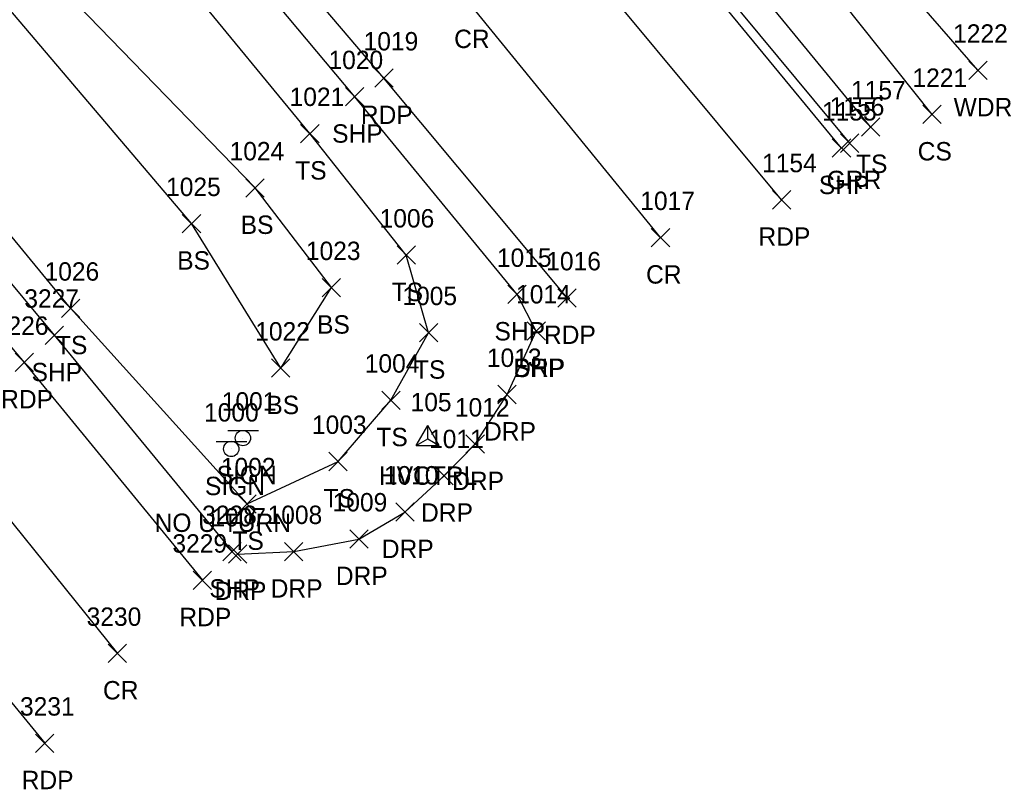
# Model space of a CAD drawing. Extents: x 1647574 to 1652703, y 212895 to 228670.
# Drawn here: x 1650120.6 to 1650228.4, y 225965.1 to 226048.7 of the extents above; entities that cross this region are included whole.
import ezdxf

# ---------------------------------------------------------------- set-up
doc = ezdxf.new("R2010")
doc.units = 0
for name, color, linetype in [('C_A', 7, 'Continuous'), ('C_I', 7, 'Continuous'), ('CPSM', 7, 'Continuous'), ('L_A', 7, 'Continuous'), ('L_I', 7, 'Continuous'), ('L_TIC', 7, 'Continuous'), ('LAWA', 7, 'Continuous'), ('LELB', 7, 'Continuous'), ('P_A', 7, 'Continuous'), ('P_I', 7, 'Continuous'), ('P_TIC', 7, 'Continuous'), ('PET', 7, 'Continuous'), ('PRC', 7, 'Continuous'), ('PSP', 7, 'Continuous'), ('R_A', 7, 'Continuous'), ('R_I', 7, 'Continuous'), ('R_TIC', 7, 'Continuous'), ('RDP', 7, 'Continuous'), ('RGR', 7, 'Continuous'), ('S_A', 7, 'Continuous'), ('S_C', 7, 'Continuous'), ('S_I', 7, 'Continuous'), ('SSGN', 7, 'Continuous')]:
    doc.layers.add(name, color=color, linetype=linetype)

msp = doc.modelspace()

# ---------------------------------------------------------------- linework, layer by layer
at = {"layer": 'CPSM'}
for p, q in [((1650163.72, 226002.47), (1650164.97, 226004.64)), ((1650166.22, 226002.47), (1650164.97, 226004.64)), ((1650164.97, 226003.19), (1650164.97, 226004.64)), ((1650163.72, 226002.47), (1650164.97, 226003.19)), ((1650163.72, 226002.47), (1650166.22, 226002.47)), ((1650164.97, 226003.19), (1650164.97, 226003.19)), ((1650164.97, 226003.19), (1650166.22, 226002.47))]:
    msp.add_line(p, q, dxfattribs=at)
at = {"layer": 'L_TIC'}
for points in [[(1650223.82, 226042.26), (1650225.82, 226044.26)], [(1650225.82, 226042.26), (1650223.82, 226044.26)], [(1650218.83, 226037.46), (1650220.83, 226039.46)], [(1650220.83, 226037.46), (1650218.83, 226039.46)], [(1650212.15, 226036.1), (1650214.15, 226038.1)], [(1650214.15, 226036.1), (1650212.15, 226038.1)], [(1650151.14, 226035.38), (1650153.14, 226037.38)], [(1650153.14, 226035.38), (1650151.14, 226037.38)], [(1650145.18, 226029.47), (1650147.18, 226031.47)], [(1650147.18, 226029.47), (1650145.18, 226031.47)], [(1650138.27, 226025.59), (1650140.27, 226027.59)], [(1650140.27, 226025.59), (1650138.27, 226027.59)], [(1650161.63, 226022.17), (1650163.63, 226024.17)], [(1650163.63, 226022.17), (1650161.63, 226024.17)], [(1650153.49, 226018.63), (1650155.49, 226020.63)], [(1650155.49, 226018.63), (1650153.49, 226020.63)], [(1650125.11, 226016.39), (1650127.11, 226018.39)], [(1650127.11, 226016.39), (1650125.11, 226018.39)], [(1650164.06, 226013.73), (1650166.06, 226015.73)], [(1650166.06, 226013.73), (1650164.06, 226015.73)], [(1650147.97, 226009.88), (1650149.97, 226011.88)], [(1650149.97, 226009.88), (1650147.97, 226011.88)], [(1650147.97, 226009.88), (1650149.97, 226011.88)], [(1650149.97, 226009.88), (1650147.97, 226011.88)], [(1650159.97, 226006.39), (1650161.97, 226008.39)], [(1650161.97, 226006.39), (1650159.97, 226008.39)], [(1650154.22, 225999.73), (1650156.22, 226001.73)], [(1650156.22, 225999.73), (1650154.22, 226001.73)], [(1650144.31, 225995.12), (1650146.31, 225997.12)], [(1650146.31, 225995.12), (1650144.31, 225997.12)], [(1650144.31, 225995.12), (1650146.31, 225997.12)], [(1650146.31, 225995.12), (1650144.31, 225997.12)]]:
    msp.add_lwpolyline(points, dxfattribs=at)
at = {"layer": 'LAWA'}
msp.add_lwpolyline([(1650224.82, 226043.26), (1650200.57, 226071.14), (1650179.14, 226096.39), (1650156.93, 226122.13), (1650126.46, 226158.5), (1650102.32, 226186.03), (1650070.86, 226221.7), (1650047.25, 226248.26), (1650033.72, 226259.55), (1650015.55, 226280.28), (1649981.36, 226313.37), (1649950.59, 226346.36), (1649922.81, 226373.8), (1649891.44, 226407.34), (1649856.77, 226439.08), (1649829.63, 226467.03), (1649787.56, 226504.18), (1649754.94, 226535.2), (1649724.22, 226565.72), (1649692.31, 226598.17), (1649653.67, 226635.29), (1649620.52, 226666.86), (1649581.67, 226703.66)], dxfattribs=at)
at = {"layer": 'LELB'}
for points in [[(1650213.15, 226037.1), (1650185.87, 226070.33), (1650156.97, 226103.72), (1650126.82, 226139.03), (1650097.45, 226172.49), (1650065.12, 226208.19), (1650039.15, 226236.7), (1650005.62, 226272.51), (1649977.06, 226302.34), (1649946.85, 226333.69), (1649915.81, 226365.02), (1649884.88, 226395.87), (1649852.74, 226426.8), (1649817.4, 226461.44), (1649778.8, 226498.35), (1649747.79, 226526.99), (1649716.78, 226556.99), (1649685.05, 226589.65), (1649647.22, 226623.29), (1649611.68, 226660.43), (1649573.8, 226694.76)], [(1650145.31, 225996.12), (1650155.22, 226000.73), (1650160.97, 226007.39), (1650165.06, 226014.73), (1650162.63, 226023.17), (1650152.14, 226036.38), (1650125.52, 226068.74), (1650101.36, 226098.15), (1650073.79, 226131.47), (1650039.14, 226169.85), (1650006.52, 226208.67), (1649978.85, 226238.77), (1649944.11, 226276), (1649910.77, 226309.61), (1649879.19, 226341.22), (1649849.26, 226371.24), (1649815.2, 226404.44), (1649786.47, 226431.97), (1649749.39, 226466.79), (1649718.31, 226495.58), (1649694.54, 226518.32), (1649659.53, 226550.77), (1649625.91, 226582.74), (1649593.12, 226613.01)], [(1650145.31, 225996.12), (1650126.11, 226017.39), (1650101.66, 226047.08), (1650074.02, 226078.27), (1650048.35, 226107.52), (1650011.02, 226148.89), (1649978.29, 226184.76), (1649948.32, 226216.56), (1649918.31, 226248.62), (1649881.09, 226286.67), (1649854.51, 226315.1), (1649822.53, 226345.57), (1649790.94, 226377.4), (1649759.46, 226406.66), (1649722.98, 226440.72), (1649699.36, 226464.18), (1649670.41, 226492.35), (1649633.05, 226526.99), (1649601.72, 226556.3), (1649565.56, 226590.44)], [(1650148.97, 226010.88), (1650139.27, 226026.59), (1650113.43, 226057), (1650088.3, 226087.98), (1650061.28, 226120.08), (1650026.24, 226159.75), (1649992.44, 226196.13), (1649963.33, 226228.07), (1649931.94, 226262.56), (1649896.29, 226297.95), (1649867.38, 226328.16), (1649836.11, 226358.29), (1649802.88, 226390.85), (1649773.49, 226418.93), (1649757.57, 226433.02), (1649733.38, 226449.67), (1649721.38, 226464.7), (1649717.89, 226468.09), (1649721.1, 226472.27), (1649725.43, 226467.47)], [(1650148.97, 226010.88), (1650154.49, 226019.63), (1650146.18, 226030.47), (1650117.14, 226060.39), (1650092.92, 226091.65), (1650065.04, 226122.85), (1650030.31, 226163.04), (1649996.06, 226198.8), (1649967.82, 226231.08), (1649935.01, 226265.64), (1649900.92, 226301.66), (1649869, 226330.3), (1649837.58, 226359.92), (1649804, 226392.67), (1649775.11, 226420.09), (1649758.52, 226434.35), (1649738.4, 226455.19), (1649725.43, 226467.47)], [(1650219.83, 226038.46), (1650194.8, 226069.92), (1650172.81, 226091.36), (1650150.41, 226121.08), (1650123.6, 226156.67)]]:
    msp.add_lwpolyline(points, dxfattribs=at)
at = {"layer": 'P_TIC'}
for points in [[(1650159.2, 226041.42), (1650161.2, 226043.42)], [(1650161.2, 226041.42), (1650159.2, 226043.42)], [(1650156.03, 226039.39), (1650158.03, 226041.39)], [(1650158.03, 226039.39), (1650156.03, 226041.39)], [(1650208.98, 226033.8), (1650210.98, 226035.8)], [(1650210.98, 226033.8), (1650208.98, 226035.8)], [(1650202.46, 226028.18), (1650204.46, 226030.18)], [(1650204.46, 226028.18), (1650202.46, 226030.18)], [(1650189.29, 226024.07), (1650191.29, 226026.07)], [(1650191.29, 226024.07), (1650189.29, 226026.07)], [(1650173.69, 226017.89), (1650175.69, 226019.89)], [(1650175.69, 226017.89), (1650173.69, 226019.89)], [(1650179.12, 226017.51), (1650181.12, 226019.51)], [(1650181.12, 226017.51), (1650179.12, 226019.51)], [(1650123.34, 226013.45), (1650125.34, 226015.45)], [(1650125.34, 226013.45), (1650123.34, 226015.45)], [(1650175.78, 226013.91), (1650177.78, 226015.91)], [(1650177.78, 226013.91), (1650175.78, 226015.91)], [(1650120.07, 226010.5), (1650122.07, 226012.5)], [(1650122.07, 226010.5), (1650120.07, 226012.5)], [(1650142.68, 225989.93), (1650144.68, 225991.93)], [(1650144.68, 225989.93), (1650142.68, 225991.93)], [(1650139.46, 225986.82), (1650141.46, 225988.82)], [(1650141.46, 225986.82), (1650139.46, 225988.82)], [(1650130.21, 225978.86), (1650132.21, 225980.86)], [(1650132.21, 225978.86), (1650130.21, 225980.86)], [(1650122.3, 225969.1), (1650124.3, 225971.1)], [(1650124.3, 225969.1), (1650122.3, 225971.1)]]:
    msp.add_lwpolyline(points, dxfattribs=at)
at = {"layer": 'PET'}
for points in [[(1650203.46, 226029.18), (1650176.21, 226061.89), (1650147.53, 226095.79), (1650117.29, 226130.73), (1650087.4, 226164.52), (1650055.9, 226199.34), (1650029.44, 226228.14), (1649996.95, 226263.47), (1649968.15, 226293.72), (1649938.19, 226324.52), (1649906.65, 226356.13), (1649876.52, 226386.27), (1649843.75, 226418.81), (1649809.66, 226451.94), (1649770.32, 226489.71), (1649739.98, 226518.42), (1649716.1, 226541.38), (1649682.51, 226572.89), (1649648.23, 226605.38), (1649615.14, 226636.4), (1649578.52, 226671.42)], [(1650180.12, 226018.51), (1650160.2, 226042.42), (1650132.53, 226074.87), (1650108.24, 226103.36), (1650079.8, 226135.84), (1650045.18, 226174.49), (1650010.43, 226212.6), (1649983.21, 226241.97), (1649947.38, 226279.71), (1649914.98, 226313), (1649883.03, 226345), (1649852.9, 226374.89), (1649819.24, 226408.27), (1649790.46, 226435.99), (1649753.36, 226471.35), (1649722.68, 226500.42), (1649698.76, 226522.75), (1649664.62, 226555.39), (1649630.41, 226587.57), (1649598.45, 226617.55), (1649561.34, 226652.9)], [(1649568.76, 226578.15), (1649602.84, 226545.72), (1649639.6, 226511.14), (1649669.58, 226482.71), (1649710.56, 226443.02), (1649749.16, 226406.1), (1649783.82, 226372.91), (1649821.53, 226335.91), (1649854.36, 226303.39), (1649893.84, 226262.84), (1649926.53, 226228.81), (1649964.59, 226188.34), (1649995.88, 226154.08), (1650026.58, 226120.39), (1650056.63, 226086.43), (1650078.17, 226061.47), (1650102.87, 226032.97), (1650121.07, 226011.5), (1650140.46, 225987.82)], [(1649585.69, 226528.77), (1649624.3, 226492.34), (1649652.1, 226465.47), (1649694.18, 226424.93), (1649731.2, 226389.82), (1649767.06, 226355.29), (1649804.34, 226318.78), (1649837.23, 226285.73), (1649875.09, 226247.37), (1649909.48, 226211.77), (1649946.37, 226172.47), (1649978.25, 226137.54), (1650007.65, 226104.95), (1650038.73, 226069.71), (1650059.42, 226046.29), (1650084.31, 226017.14), (1650102.55, 225995.44), (1650123.3, 225970.1)]]:
    msp.add_lwpolyline(points, dxfattribs=at)
at = {"layer": 'PRC'}
for points in [[(1650190.29, 226025.07), (1650169.4, 226050.68), (1650141.73, 226083.3), (1650117.9, 226111.09), (1650088.92, 226144.57), (1650053.94, 226182.93), (1650019.72, 226220.45), (1649992.16, 226250.42), (1649956.56, 226288.56), (1649923.88, 226321.79), (1649891.54, 226354.39), (1649861.68, 226384.4), (1649827.7, 226416.9), (1649798.54, 226445.37), (1649761.96, 226480.16), (1649731.42, 226509.46), (1649707.37, 226531.84), (1649673.7, 226564), (1649639.62, 226596.15), (1649606.75, 226626.95), (1649570.25, 226661.64)], [(1649559.91, 226569.96), (1649593.92, 226537.25), (1649631.94, 226502.23), (1649660.46, 226474.34), (1649702.15, 226434.36), (1649740.4, 226397.48), (1649775.04, 226364.12), (1649813.32, 226327.22), (1649846.03, 226294.55), (1649884.93, 226255.04), (1649918.06, 226220.06), (1649955.14, 226180.9), (1649987.04, 226146.06), (1650016.78, 226113.16), (1650047.62, 226077.89), (1650069.26, 226053.4), (1650093.06, 226025.47), (1650111.86, 226003.86), (1650131.21, 225979.86)]]:
    msp.add_lwpolyline(points, dxfattribs=at)
at = {"layer": 'PSP'}
for points in [[(1650209.98, 226034.8), (1650182.89, 226067.68), (1650153.83, 226101.81), (1650124.05, 226136.25), (1650094.35, 226170.32), (1650062.83, 226205.52), (1650036.19, 226234.57), (1650003.11, 226270.29), (1649975.25, 226299.75), (1649944.68, 226331.46), (1649913.77, 226362.55), (1649883.23, 226393.29), (1649850.54, 226425.12), (1649815.25, 226459.11), (1649776.56, 226495.81), (1649746.09, 226524.83), (1649714.65, 226554.46), (1649681.67, 226585.65), (1649644.69, 226620.23), (1649606.95, 226655.87), (1649570.92, 226690.01)], [(1650176.78, 226014.91), (1650174.69, 226018.89), (1650157.03, 226040.39), (1650129.97, 226072.67), (1650105.28, 226101.15), (1650076.93, 226133.75), (1650041.79, 226172.07), (1650008.03, 226209.64), (1649980.35, 226240.01), (1649944.97, 226277.48), (1649912.15, 226310.56), (1649880.37, 226342.42), (1649850.35, 226372.48), (1649816.61, 226405.58), (1649787.78, 226433.35), (1649750.91, 226468.71), (1649720.44, 226497.53), (1649696.48, 226520.16), (1649661.7, 226552.53), (1649627.77, 226584.84), (1649595.64, 226615.02), (1649558.33, 226650.15)], [(1649571.18, 226581.28), (1649605.62, 226548.46), (1649642.47, 226514.36), (1649673.51, 226485.11), (1649713.05, 226446.56), (1649753.13, 226408.58), (1649786.75, 226376.31), (1649825.02, 226339.17), (1649858.01, 226306.81), (1649897.5, 226266.11), (1649930.08, 226232.3), (1649968.22, 226191.53), (1649999.65, 226157.4), (1650029.99, 226123.79), (1650060.42, 226089.05), (1650081.82, 226064.3), (1650106.87, 226035.38), (1650124.34, 226014.45), (1650143.68, 225990.93)]]:
    msp.add_lwpolyline(points, dxfattribs=at)
at = {"layer": 'R_TIC'}
for points in [[(1650209.88, 226034.34), (1650211.88, 226036.34)], [(1650211.88, 226034.34), (1650209.88, 226036.34)], [(1650175.78, 226013.91), (1650177.78, 226015.91)], [(1650177.78, 226013.91), (1650175.78, 226015.91)], [(1650172.6, 226007.01), (1650174.6, 226009.01)], [(1650174.6, 226007.01), (1650172.6, 226009.01)], [(1650169.13, 226001.62), (1650171.13, 226003.62)], [(1650171.13, 226001.62), (1650169.13, 226003.62)], [(1650165.75, 225998.18), (1650167.75, 226000.18)], [(1650167.75, 225998.18), (1650165.75, 226000.18)], [(1650161.48, 225994.23), (1650163.48, 225996.23)], [(1650163.48, 225994.23), (1650161.48, 225996.23)], [(1650156.48, 225991.3), (1650158.48, 225993.3)], [(1650158.48, 225991.3), (1650156.48, 225993.3)], [(1650143.28, 225989.67), (1650145.28, 225991.67)], [(1650145.28, 225989.67), (1650143.28, 225991.67)], [(1650149.39, 225989.93), (1650151.39, 225991.93)], [(1650151.39, 225989.93), (1650149.39, 225991.93)]]:
    msp.add_lwpolyline(points, dxfattribs=at)
at = {"layer": 'RDP'}
msp.add_lwpolyline([(1650144.28, 225990.67), (1650150.39, 225990.93), (1650157.48, 225992.3), (1650162.48, 225995.23), (1650166.75, 225999.18), (1650170.13, 226002.62), (1650173.6, 226008.01), (1650176.78, 226014.91)], dxfattribs=at)
at = {"layer": 'RGR'}
msp.add_lwpolyline([(1650210.88, 226035.34), (1650183.47, 226068.36), (1650154.6, 226102.18), (1650124.72, 226137.1), (1650095.1, 226170.93), (1650063.42, 226206.14), (1650036.95, 226235.01), (1650003.69, 226270.69), (1649975.87, 226300.38), (1649945.2, 226332.04), (1649914.34, 226363.19), (1649883.95, 226393.7), (1649851.2, 226425.71), (1649815.73, 226459.46), (1649777.08, 226496.44), (1649746.45, 226525.34), (1649715.22, 226555.07), (1649682.27, 226586.18), (1649645.22, 226621.05), (1649607.54, 226656.38), (1649571.29, 226690.65)], dxfattribs=at)
at = {"layer": 'SSGN'}
for p, q in [((1650143.21, 226004.11), (1650146.55, 226004.11)), ((1650144.86, 226003.28), (1650144.86, 226003.28)), ((1650141.94, 226002.92), (1650145.28, 226002.92)), ((1650143.59, 226002.09), (1650143.59, 226002.09))]:
    msp.add_line(p, q, dxfattribs=at)
for centre in [(1650144.86, 226003.28), (1650143.59, 226002.09)]:
    msp.add_circle(centre, 0.833, dxfattribs=at)

# ---------------------------------------------------------------- texts
at = {"layer": 'C_A'}
msp.add_text('HVCTRL', height=2, dxfattribs=at).set_placement((1650159.66, 225998.19))
at = {"layer": 'C_I'}
msp.add_text('105', height=2, dxfattribs=at).set_placement((1650163.1, 226006.19))
at = {"layer": 'L_A'}
for s, p in [('WDR', (1650222.18, 226038.26)), ('CS', (1650218.27, 226033.46)), ('TS', (1650211.56, 226032.1)), ('TS', (1650150.55, 226031.38)), ('BS', (1650144.62, 226025.47)), ('BS', (1650137.71, 226021.59)), ('TS', (1650161.04, 226018.17)), ('BS', (1650152.93, 226014.63)), ('TS', (1650124.52, 226012.39)), ('TS', (1650163.47, 226009.73)), ('BS', (1650147.41, 226005.88)), ('BS', (1650147.41, 226005.88)), ('TS', (1650159.38, 226002.39)), ('TS', (1650153.63, 225995.73)), ('TS', (1650143.72, 225991.12)), ('TS', (1650143.72, 225991.12))]:
    msp.add_text(s, height=2, dxfattribs=at).set_placement(p)
at = {"layer": 'L_I'}
for s, p in [('1222', (1650222.12, 226046.26)), ('1221', (1650217.7, 226041.46)), ('1157', (1650211.02, 226040.1)), ('1021', (1650149.94, 226039.38)), ('1024', (1650143.41, 226033.47)), ('1025', (1650136.5, 226029.59)), ('1006', (1650159.73, 226026.17)), ('1023', (1650151.71, 226022.63)), ('1026', (1650123.28, 226020.39)), ('1005', (1650162.21, 226017.73)), ('1022', (1650146.2, 226013.88)), ('1022', (1650146.2, 226013.88)), ('1004', (1650158.12, 226010.39)), ('1003', (1650152.37, 226003.73)), ('1002', (1650142.46, 225999.12)), ('1002', (1650142.46, 225999.12))]:
    msp.add_text(s, height=2, dxfattribs=at).set_placement(p)
at = {"layer": 'P_A'}
for s, p in [('CR', (1650167.84, 226045.68)), ('RDP', (1650157.69, 226037.42)), ('SHP', (1650154.57, 226035.39)), ('SHP', (1650207.52, 226029.8)), ('RDP', (1650200.95, 226024.18)), ('CR', (1650188.72, 226020.07)), ('SHP', (1650172.23, 226013.89)), ('RDP', (1650177.61, 226013.51)), ('SHP', (1650174.32, 226009.91)), ('SHP', (1650121.87, 226009.45)), ('RDP', (1650118.56, 226006.5)), ('SHP', (1650141.21, 225985.93)), ('RDP', (1650137.95, 225982.82)), ('CR', (1650129.64, 225974.86)), ('RDP', (1650120.79, 225965.1))]:
    msp.add_text(s, height=2, dxfattribs=at).set_placement(p)
at = {"layer": 'P_I'}
for s, p in [('1019', (1650157.99, 226045.42)), ('1020', (1650154.17, 226043.39)), ('1155', (1650207.86, 226037.8)), ('1154', (1650201.34, 226032.18)), ('1017', (1650188.09, 226028.07)), ('1015', (1650172.49, 226021.89)), ('1016', (1650177.86, 226021.51)), ('3227', (1650121.08, 226017.45)), ('1014', (1650174.58, 226017.91)), ('3226', (1650117.76, 226014.5)), ('3228', (1650140.42, 225993.93)), ('3229', (1650137.19, 225990.82)), ('3230', (1650127.86, 225982.86)), ('3231', (1650120.61, 225973.1))]:
    msp.add_text(s, height=2, dxfattribs=at).set_placement(p)
at = {"layer": 'R_A'}
for s, p in [('GRR', (1650208.37, 226030.34)), ('DRP', (1650174.27, 226009.91)), ('DRP', (1650171.09, 226003.01)), ('DRP', (1650167.62, 225997.62)), ('DRP', (1650164.24, 225994.18)), ('DRP', (1650159.97, 225990.23)), ('DRP', (1650154.97, 225987.3)), ('DRP', (1650141.77, 225985.67)), ('DRP', (1650147.88, 225985.93))]:
    msp.add_text(s, height=2, dxfattribs=at).set_placement(p)
at = {"layer": 'R_I'}
for s, p in [('1156', (1650208.7, 226038.34)), ('1014', (1650174.58, 226017.91)), ('1013', (1650171.4, 226011.01)), ('1012', (1650167.92, 226005.62)), ('1011', (1650165.11, 226002.18)), ('1010', (1650160.19, 225998.23)), ('1009', (1650154.62, 225995.3)), ('1007', (1650141.43, 225993.67)), ('1008', (1650147.54, 225993.93))]:
    msp.add_text(s, height=2, dxfattribs=at).set_placement(p)
at = {"layer": 'S_A'}
for p in [(1650142, 225998.26), (1650140.73, 225997.07)]:
    msp.add_text('SIGN', height=2, dxfattribs=at).set_placement(p)
at = {"layer": 'S_C'}
msp.add_text('NO U TURN', height=2, dxfattribs=at).set_placement((1650135.25, 225993.07))
at = {"layer": 'S_I'}
for s, p in [('1001', (1650142.56, 226006.26)), ('1000', (1650140.63, 226005.07))]:
    msp.add_text(s, height=2, dxfattribs=at).set_placement(p)

doc.saveas('drawing.dxf')
